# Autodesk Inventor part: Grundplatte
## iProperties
Created: 2009-12
Part Number: Grundplatte
Document SubType Name: Modeling
Designer: AEW
Mass: 1962.5 g
Surface Area: 570 cm^2
Volume: 250 cm^3
Density: 7.85 g/cm^3
Material: Stahl
Author: AEW
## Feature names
1. Extrusion1
